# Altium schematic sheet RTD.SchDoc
size 431 x 279 mm; Organization: ORGANIZATION; Address1: ADDRESS 1; Address2: ADDRESS 2; Address3: ADDRESS 3; Address4: ADDRESS 4; Revision: -; ENG_APP_DATE: --/--/--; DSN_APP_DATE: --/--/--; CHK_APP_DATE: --/--/--
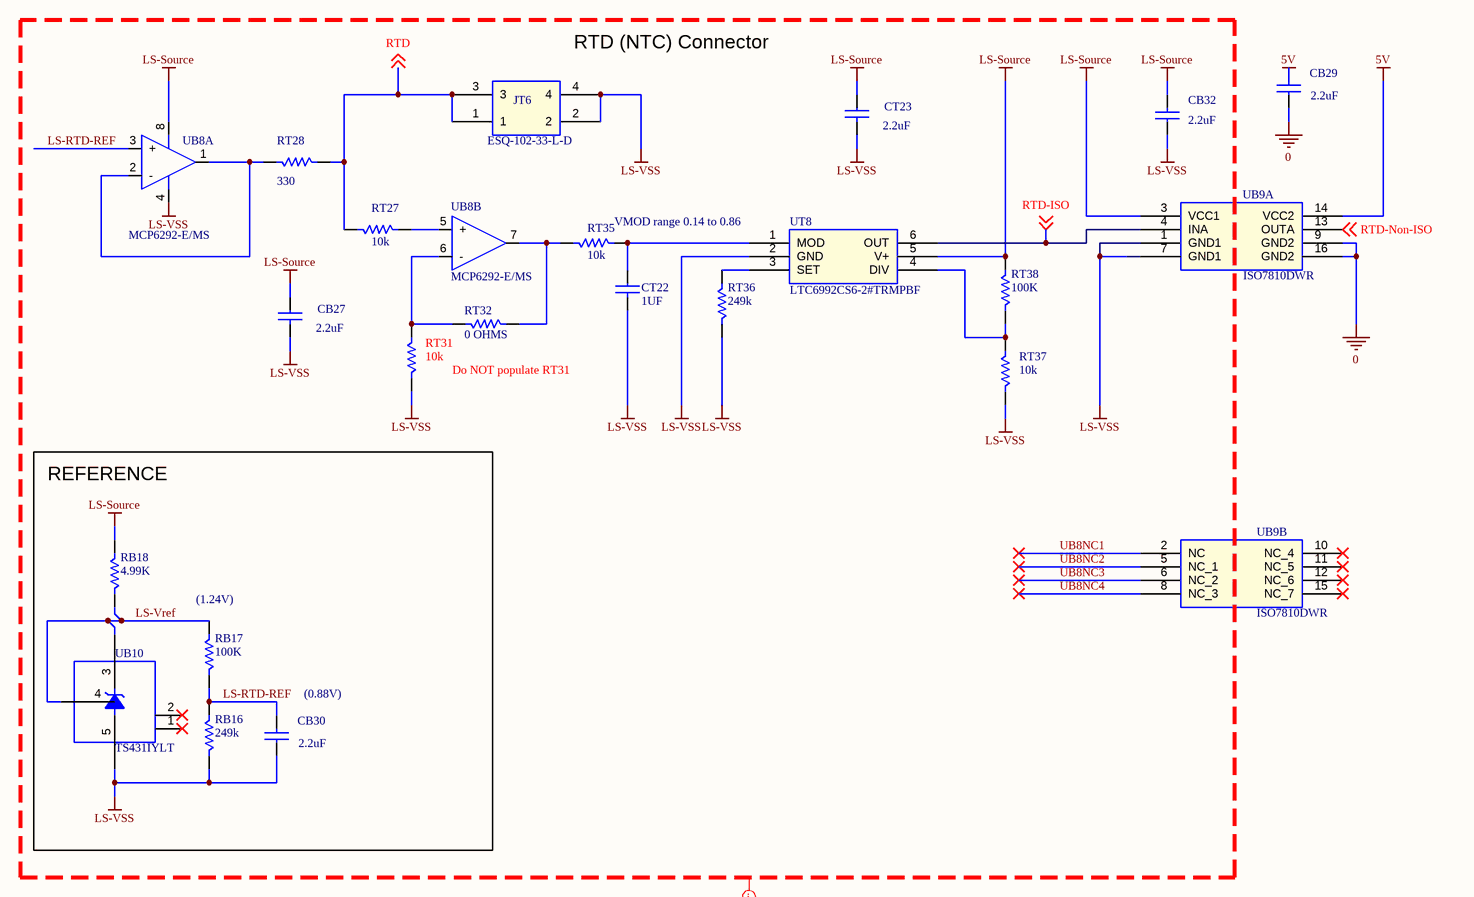
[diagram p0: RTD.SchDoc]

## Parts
CB27  2.2uF  [CAPC1608X90N]
CB29  2.2uF  [CAPC1608X90N]
CB30  2.2uF  [CAPC1608X90N]
CB32  2.2uF  [CAPC1608X90N]
CT22  1UF  [CAPC1608X90N]
CT23  2.2uF  [CAPC1608X90N]
JT6  ESQ-102-33-L-D  [CON_2x2_100mil_TH]
RB16  249k  [RESC1608X06N]
RB17  100K  [RESC1608X06N]
RB18  4.99K  [RESC1608X06N]
RT27  10k  [RESC1608X55N]
RT28  330  [RESC1608X55N]
RT31  10k  [RESC1608X55N]
RT32  0 OHMS  [RESC1608X55N]
RT35  10k  [RESC1608X55N]
RT36  249k  [RESC1608X06N]
RT37  10k  [RESC1608X55N]
RT38  100K  [RESC1608X06N]
UB8  MCP6292-E/MS  [TSOP65P580X110-8N]  (parts A,B of 2)
UB9  ISO7810DWR  [SOIC127P1030X265-16N]  (parts A,B of 2)
UB10  TS431IYLT  [SOT95P280X145-5N]
UT8  LTC6992CS6-2#TRMPBF  [SOT95P280X100-6N]

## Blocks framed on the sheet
REFERENCE: CB30 RB16-RB18 UB10

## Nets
0: CB29.1 UB9.9(GND2) UB9.16(GND2)
5V: CB29.2 UB9.14(VCC2)
LS-Source: CB27.1 CB32.2 CT23.1 RB18.1 RT38.1 UB8.8(VDD) UB9.3(VCC1) UT8.5(V+)
LS-VSS: CB27.2 CB30.1 CB32.1 CT22.2 CT23.2 JT6.2 JT6.4 RB16.2 RT31.1 RT36.2 RT37.1 UB8.4(VSS) UB9.1(GND1) UB9.7(GND1) UB10.5(C) UT8.2(GND)
LS-RTD-REF: CB30.2 RB16.1 RB17.2 UB8.3(+)
LS-Vref: RB17.1 RB18.2 UB10.3(REF) UB10.4
RTD: JT6.1 JT6.3 RT27.2 RT28.2 ; off-sheet RTD
RTD-ISO: UB9.4(INA) UT8.6(OUT) ; off-sheet RTD-ISO
RTD-Non-ISO: UB9.13(OUTA) ; off-sheet RTD-Non-ISO
UB8NC1: UB9.2(NC)
UB8NC2: UB9.5(NC_1)
UB8NC3: UB9.6(NC_2)
UB8NC4: UB9.8(NC_3)
NetCT22_1: CT22.1 RT35.1 UT8.1(MOD)
NetRT27_1: RT27.1 UB8.5(+)
NetRT28_1: RT28.1 UB8.1(VOUTA) UB8.2(-)
NetRT31_2: RT31.2 RT32.1 UB8.6(-)
NetRT32_2: RT32.2 RT35.2 UB8.7(VOUTB)
NetRT36_1: RT36.1 UT8.3(SET)
NetRT37_2: RT37.2 RT38.2 UT8.4(DIV)

Not connected (* = marked no-connect by the designer): UB9 10(NC_4)* 11(NC_5)* 12(NC_6)* 15(NC_7)*; UB10 1(NC)* 2(NC)*

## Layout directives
net class LS_Nets: LS-RTD-REF, LS-Source, LS-Vref, LS-VSS, RTD, RTD-ISO, UB8NC1, UB8NC2, UB8NC3, UB8NC4

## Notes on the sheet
- (near JT6) RTD (NTC) Connector
- (near RT35) VMOD range 0.14 to 0.86
- Do NOT populate RT31
- (near RB17) (1.24V)
- (near CB30) (0.88V)

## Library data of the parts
CB27 CT23 = CAP_2.2uF: CAP CER 2.2UF 50V X5R 0603; Company Part Status: Obsolete; Manufacturer: Murata Electronics North America; Manufacturer PN: GRT188R61H225ME13D; Tolerance: 20%; CLASS: DISCRETE
CB29 CB30 = CAP_2.2uF: CAP CER 2.2UF 50V X5R 0603; Manufacturer PN: GRT188R61H225ME13D; Manufacturer: Murata Electronics North America; Company Part Status: Obsolete; CLASS: DISCRETE; Tolerance: 20%
CB32 = CAP_2.2uF: CAP CER 2.2UF 50V X5R 0603; Manufacturer: Murata Electronics North America; Manufacturer PN: GRT188R61H225ME13D; Company Part Status: Obsolete; Tolerance: 20%; CLASS: DISCRETE
CT22 = CAP_1UF: CAP CER 1UF 10V X7R 0603; Manufacturer: Samsung; Manufacturer Part Number: CL10B105KP8NNNC; Tolerance: 10%
JT6 = CON_2x2_100mil: Conn Elevated Socket SKT 4 POS 2.54mm Solder ST Thru-Hole; Manufacturer: Samtec; CLASS: IO; Number of Contacts: 4; Gender: Receptacle
RB16 = RES_9_BOTTOM: RES 249K OHM 1% 1/10W 0603; Manufacturer: Yageo; Manufacturer Part Number: RC0603FR-07249KL; Voltage Rating: 50V; Resistance: 249kR; Power Rating: 100mW; Temperature Coefficient: 100ppm/°C
RB17 = RES_10B: RES SMD 100K OHM 1% 1/10W 0603; Manufacturer: TE Connectivity; Manufacturer Part Number: CRG0603F100K; Resistance: 100kR; Temperature Coefficient: 100ppm/°C; Power Rating: 100mW; Voltage Rating: 50V; Number of Resistors: 1; Class Name: LS_Components
RB18 = RES_11: RES 4.99K OHM 1% 1/10W 0603; Manufacturer: Yageo; Manufacturer Part Number: RC0603FR-074K99L; Resistance: 4.99kR; Voltage Rating: 75V; Power Rating: 100mW; Temperature Coefficient: 100ppm/°C; Voltage Rating (DC): 50V
RT27 RT35 RT37 = RES: RES SMD 10K OHM 1% 1/10W 0603; Manufacturer PN: ERJ-3EKF1002V; Manufacturer: Panasonic Electronic Components; Company Part Status: New; PART_NUMBER: TMP-788; CLASS: DISCRETE; Rated Power: 0.1W, 1/10W; Temperature Coefficient: 100ppm/C
RT28 = RES_3: RES SMD 330 OHM 5% 1/10W 0603; Manufacturer PN: RC0603JR-07330RL; Manufacturer: Yageo; Company Part Status: Released; CLASS: DISCRETE; Rated Power: 0.1W, 1/10W; Temperature Coefficient: 100ppm/C
RT31 = RES: RES SMD 10K OHM 1% 1/10W 0603; Manufacturer PN: ERJ-3EKF1002V; Manufacturer: Panasonic Electronic Components; Company Part Status: New; PART_NUMBER: TMP-788; CLASS: DISCRETE; Rated Power: 0.1W, 1/10W; Temperature Coefficient: 100ppm/C; Class Name: LS_Components
RT32 = RES_12: RES 0 OHM JUMPER 0603; Manufacturer: Vishay Dale; Manufacturer Part Number: WSL060300000ZEA9; Resistance: 0mR
RT36 = RES_9_TOP: RES 249K OHM 1% 1/10W 0603; Manufacturer: Yageo; Manufacturer Part Number: RC0603FR-07249KL; Voltage Rating: 50V; Resistance: 249kR; Power Rating: 100mW; Temperature Coefficient: 100ppm/°C; Class Name: LS_Components
RT38 = RES_10: RES SMD 100K OHM 1% 1/10W 0603; Manufacturer: TE Connectivity; Manufacturer Part Number: CRG0603F100K; Resistance: 100kR; Temperature Coefficient: 100ppm/°C; Power Rating: 100mW; Voltage Rating: 50V; Number of Resistors: 1; Class Name: LS_Components
UB8 = MCP6292-E/MS: IC OPAMP GP 2 CIRCUIT 8MSOP; Manufacturer: Microchip; Number of Channels: 2; Max Supply Voltage: 5.5V; Unity Gain Bandwidth Product: 10MHz; Slew Rate: 7V/µs; Common Mode Rejection Ratio: 70dB; Min Supply Voltage: 2.4V; Voltage Gain: 110dB; Output Current: 25mA; Nominal Supply Current: 1mA; Input Bias Current: 1pA; Input Offset Voltage (Vos): 3mV; Amplifier Type: GENERAL PURPOSE; Input Offset Voltage-Max: 5mV
UB9 = ISO7810DWR: DGTL ISO 5.7KV GEN PURP 16SOIC; Company Part Status: Released; Built_By: TexasInstrumentTeam; PACK_SHORT: (GND1,GND1_1),(GND2,GND2_1); Vendor: Texas Instruments; Supply Voltage: 2.25V ~ 5.5V; CLASS: IC; PCB Footprint: DW0016B_N
UB10 = TS431IYLT: IC VREF SHUNT ADJ 2% SOT23-5; Manufacturer: STMicroelectronics; Output Voltage: 6V; Max Input Voltage: 10V; Max Output Current: 30mA; Reference Type: Shunt,Adjustable; Number of Channels: 1; Temperature Coefficient: 100ppm/°C; Cathode Current: 60uA; Output Type: Adjustable; Min Output Voltage: 1.24V
UT8 = LTC6992CS6-2: IC OSC SILICON PROG TSOT23-6; Manufacturer: Analog Devices / Linear Technology; Frequency: 3.81Hz; Min Supply Voltage: 2.25V; Max Supply Voltage: 5.5V; Number of Timers/Counters: 1; Operating Supply Current: 365uA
